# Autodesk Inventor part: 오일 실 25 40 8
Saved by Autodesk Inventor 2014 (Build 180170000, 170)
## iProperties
Created: 2026-04
Part Number: 오일 실 25 40 8
Material: 고무
Document SubType Name: Modeling
Designer: dg
Density: 0.93 g/cm^3
Appearance: 고무 - 검은색 - 버전 1.1
Mass: 2.48215 g
Surface Area: 40.3381 cm^2
Volume: 2.66898 cm^3
Author: jhkim
Description: 오일-실
Creation Date: 2026-03-27
Sending System: Autodesk Inventor 2026
Preprocessor: ST-DEVELOPER v20.1
Author: dg
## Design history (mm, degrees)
node "오일 실 25 40 81"
body "Solid1"
node "기준1"
